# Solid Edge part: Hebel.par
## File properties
Author: helmut
Template: Normal.par
Last saved by: helmut
Revision: 4
Application: Solid Edge
Teilflächenrmatvorlage: Model Default
Coef. of Thermal Exp: 0.0
Thermal Conductivity: 0.0
Specific Heat: 0.0
Modulus of Elasticity: 0.0
Poission's Ratio: 0.0
Yield Stress: 0.0
Ultimate Stress: 0.0
Elongation: 0.0
Dichte: 7,79999702546 kg/dm^3
Genauigkeit: 0,010
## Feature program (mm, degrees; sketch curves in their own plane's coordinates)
sketch for "unnamed Protrusion 1" plane through (0, 0, 0) normal (0, -1, 0) x-axis (1, 0, 0)
  line (-6.5, 0) -> (6.5, 0)
  line (6.5, 0) -> (6.5, 6.5)
  line (6.5, 6.5) -> (-6.5, 6.5)
  line (-6.5, 6.5) -> (-6.5, 0)
  dimension (linear) = 6.5
  dimension (linear) = 6.5
extrude "unnamed Protrusion 1" add finite 200 along -normal
sketch for "Bohrung_1" plane through (0, 100, 6.5) normal (0, 0, 1) x-axis (0, 1, 0)
  hole centre (92, 0) bore radius 3
hole "Bohrung_1" diameter 6 through
sketch for "unnamed Hole 1" plane through (0, 100, 6.5) normal (0, 0, 1) x-axis (0, 1, 0)
  hole centre (-92, 0) bore radius 3
hole "unnamed Hole 1" through
pattern "unnamed Pattern 1" of "Bohrung_1", "unnamed Hole 1"
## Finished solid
Body 1: solid body, 8 faces, 16 edges, 8 vertices.
  Faces by surface: plane 6, cylinder 2
  Edges by curve: line 12, circle 4
Bounding box of the edges (mm): 13.000 x 200.000 x 6.500, from (-6.5, 0, 0) to (6.5, 200, 6.5).
Cylindrical faces by radius (mm): R3 x2
Planar faces by outward normal: +x 1, +y 1, +z 1, -x 1, -y 1, -z 1
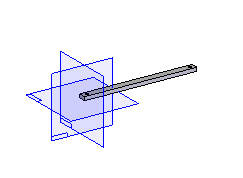
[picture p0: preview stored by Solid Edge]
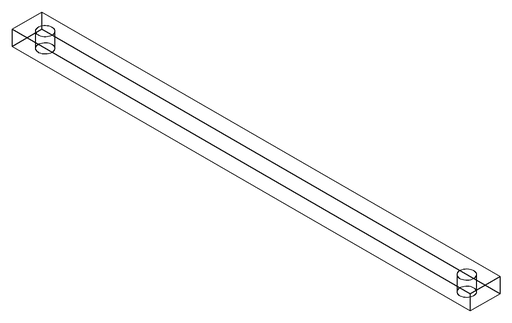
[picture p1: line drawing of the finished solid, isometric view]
